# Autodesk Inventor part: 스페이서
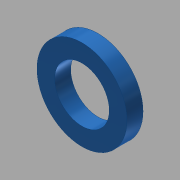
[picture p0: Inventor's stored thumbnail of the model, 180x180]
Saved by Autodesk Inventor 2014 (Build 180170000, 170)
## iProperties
Created: 2018-01
Part Number: 스페이서
Material: 스테인리스강
Document SubType Name: Modeling
Designer: mduedu
Density: 8.08 g/cm^3
Appearance: 청록색
Mass: 1.9633 g
Surface Area: 3.71101 cm^2
Volume: 0.242983 cm^3
Author: mduedu
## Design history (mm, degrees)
sketch "스케치1"
  geometry: C1 r 7 at (0, 0); C2 r 4.25 at (0, 0); 1 further point
  constraints: 2 centre point, 2 coincident
  dimensions: "d0" = 14 diameter of C1; "d1" = 8.5 diameter of C2
extrude "돌출1" new body sketch "스케치1" distance "d2" = 2.5; taper "d3" = 0 deg
node "솔리드1"
